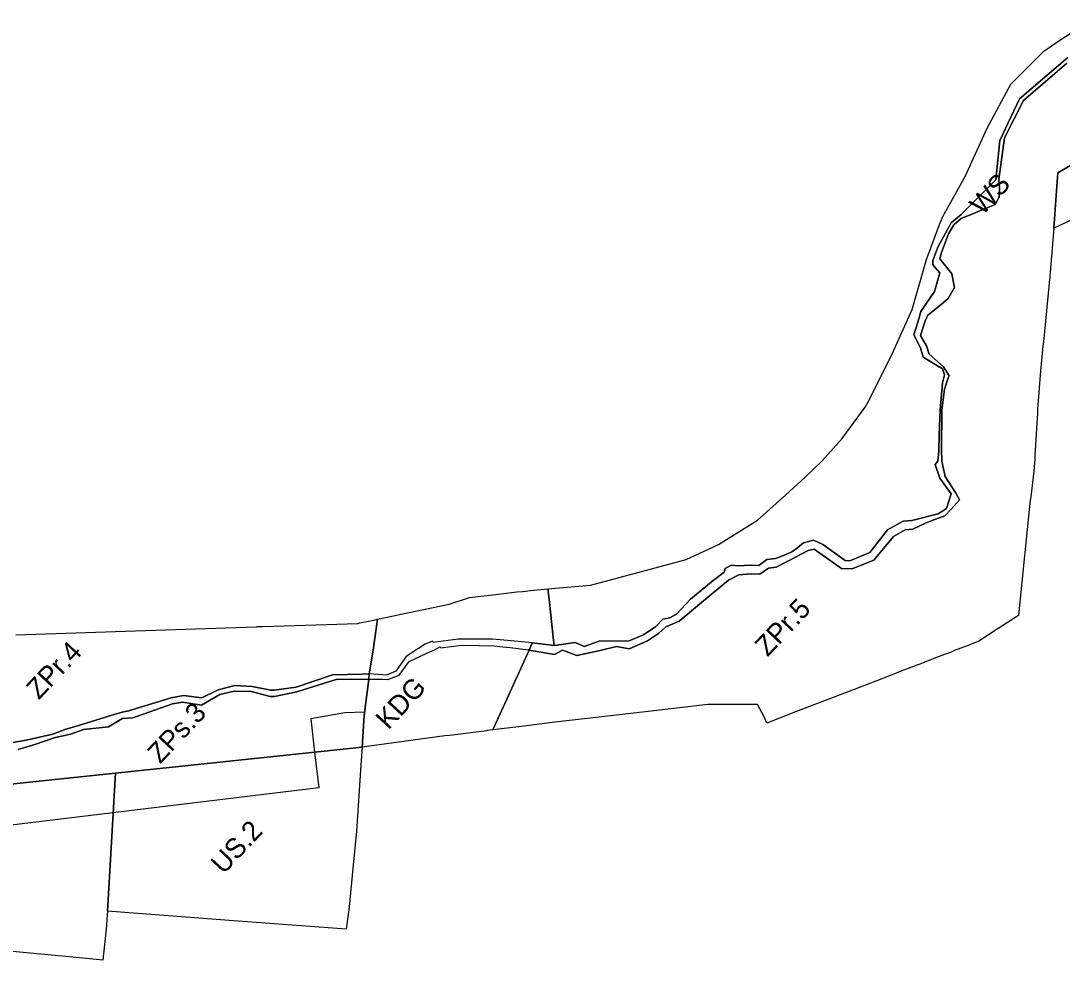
# Model space of a CAD drawing. Extents: x 7425782 to 7428854, y 5550411 to 5553074.
# Drawn here: x 7426386.8 to 7426859.1, y 5550939.3 to 5551365.3 of the extents above; entities that cross this region are included whole.
import ezdxf

# ---------------------------------------------------------------- set-up
doc = ezdxf.new("R2010")
doc.units = 0
for name, color, linetype in [('LIN_Linie rozgraniczajace WS', 7, 'Continuous'), ('LIN_linie_rozgraniczajace', 7, 'Continuous'), ('LIN_nieprzekraczalna linia zabudowy', 7, 'Continuous'), ('TXT_oznaczenia przeznaczen', 7, 'Continuous')]:
    doc.layers.add(name, color=color, linetype=linetype)

msp = doc.modelspace()

# ---------------------------------------------------------------- linework, layer by layer
at = {"layer": 'LIN_Linie rozgraniczajace WS'}
for points in [[(7426544.64, 5551066.75), (7426550.76, 5551066.7), (7426553.24, 5551066.62), (7426558.34, 5551068.56), (7426562.97, 5551074.77), (7426570.95, 5551078.5), (7426574.73, 5551080.15), (7426576.86, 5551081.45), (7426577.3, 5551080.86), (7426586.6, 5551082.15), (7426594.58, 5551081.99), (7426601.49, 5551081.78), (7426605.34, 5551081.36), (7426608.7, 5551081), (7426617.09, 5551079.96), (7426617.26, 5551079.93)], [(7426618.72, 5551083.15), (7426605.85, 5551084.33), (7426600.71, 5551084.81), (7426595.33, 5551084.81), (7426585.2, 5551084.85), (7426573.72, 5551083.35), (7426573.52, 5551084.02), (7426570.22, 5551082.64), (7426561.54, 5551076.92), (7426556.92, 5551070.28), (7426552.59, 5551068.57), (7426550.96, 5551068.63), (7426544.81, 5551069.07)]]:
    msp.add_lwpolyline(points, dxfattribs=at)
at = {"layer": 'LIN_linie_rozgraniczajace'}
for points in [[(7426861.62, 5551348.67), (7426839.69, 5551329.93), (7426830.84, 5551310.94), (7426828.92, 5551293.15), (7426813.19, 5551277.45), (7426808.67, 5551273.65), (7426802.7, 5551262.61), (7426800.34, 5551256.53), (7426800.44, 5551254.63), (7426803.55, 5551250.97), (7426801.13, 5551242.5), (7426795.01, 5551233.52), (7426794.5, 5551231.86), (7426794.19, 5551230.58), (7426791.84, 5551222.83), (7426794.76, 5551217.02), (7426796.02, 5551212.76), (7426804.8, 5551207.39), (7426805.63, 5551204.67), (7426804.72, 5551201.14), (7426803.73, 5551188.85), (7426803.34, 5551177.38), (7426803.16, 5551170.19), (7426802.7, 5551165.74), (7426802.04, 5551164.8), (7426801.52, 5551164.07), (7426803.58, 5551157.82), (7426808.73, 5551150.74), (7426806.57, 5551144.13), (7426802.84, 5551141.74), (7426790.86, 5551138.66), (7426787.01, 5551138.42), (7426779.87, 5551134.49), (7426771.89, 5551124.09), (7426762.83, 5551120.43), (7426760.72, 5551120.47), (7426750.52, 5551127.82), (7426746.29, 5551129.76), (7426741.82, 5551128.55), (7426738.96, 5551126.29), (7426736.47, 5551124.46), (7426733.43, 5551123.09), (7426728.99, 5551121.47), (7426725.12, 5551121.04), (7426721.48, 5551118.25), (7426717.63, 5551118.42), (7426712.16, 5551118.06), (7426708.98, 5551118.44), (7426706.16, 5551116.93), (7426705.81, 5551115.26), (7426700.73, 5551111.47), (7426690.46, 5551103.03), (7426684.12, 5551096.22), (7426681.09, 5551094.53), (7426678.02, 5551093.89), (7426674.76, 5551090.67), (7426669.15, 5551086.76), (7426662.62, 5551084.17), (7426649.14, 5551083.89), (7426642.26, 5551081.59), (7426638.9, 5551083.1), (7426638.25, 5551083.38), (7426628.65, 5551081.97), (7426628.2, 5551085.55), (7426626.49, 5551101.61), (7426625.83, 5551107.75), (7426645.13, 5551109.28), (7426647.39, 5551109.9), (7426666.64, 5551115.09), (7426688.49, 5551120.97), (7426703.26, 5551127.83), (7426720.86, 5551138.77), (7426733.58, 5551150.18), (7426742.45, 5551158.35), (7426750, 5551165.54), (7426759.3, 5551175.85), (7426769.77, 5551190.12), (7426771.1, 5551192.54), (7426781.46, 5551213.13), (7426791.01, 5551234.34), (7426797.59, 5551257.05), (7426803.48, 5551272.98), (7426804.91, 5551276.61), (7426815.07, 5551294.63), (7426824.99, 5551316.59), (7426835.75, 5551336.51), (7426850.74, 5551351.48), (7426858.52, 5551356.89), (7426871.59, 5551365.28)], [(7426861.25, 5551346.13), (7426841.49, 5551329.22), (7426832.91, 5551312.28), (7426830.27, 5551293.32), (7426830.69, 5551289.51), (7426830.48, 5551285.25), (7426829.17, 5551282.83), (7426828.35, 5551281.88), (7426823.87, 5551280.05), (7426819.56, 5551278.26), (7426813.3, 5551275.65), (7426809.94, 5551272.69), (7426807.56, 5551268.65), (7426804.38, 5551260.25), (7426803.58, 5551257.37), (7426809.07, 5551250.6), (7426810.19, 5551244.28), (7426807.41, 5551239.31), (7426805.15, 5551237.46), (7426797.98, 5551231.57), (7426797.47, 5551230.42), (7426796.99, 5551229.18), (7426794.77, 5551222.64), (7426797.6, 5551217.87), (7426798.74, 5551214.13), (7426805.2, 5551208.35), (7426807.82, 5551204.22), (7426807.36, 5551203.39), (7426805.74, 5551198.25), (7426804.47, 5551188.7), (7426804.41, 5551170.61), (7426804.42, 5551165.75), (7426804.91, 5551163.46), (7426805.93, 5551158.68), (7426810.68, 5551151.3), (7426812.47, 5551147.99), (7426808.75, 5551143.82), (7426805.91, 5551140.78), (7426800.17, 5551138.65), (7426797.4, 5551137.61), (7426791.28, 5551134.78), (7426787.8, 5551134.44), (7426782.56, 5551131.34), (7426773.59, 5551120.61), (7426764.95, 5551117.16), (7426763.79, 5551116.69), (7426758.93, 5551116.91), (7426746.53, 5551125.69), (7426743.84, 5551125.07), (7426740.69, 5551123.37), (7426734.89, 5551120.35), (7426729.34, 5551117.48), (7426725.82, 5551117.04), (7426721.99, 5551114.33), (7426718.04, 5551114.53), (7426712.46, 5551114.07), (7426707.71, 5551111.67), (7426695.53, 5551101.51), (7426685.36, 5551093.06), (7426679.24, 5551090.38), (7426675.99, 5551087.44), (7426670.94, 5551084.1), (7426662.68, 5551080.41), (7426656.97, 5551081.5), (7426649.6, 5551079.71), (7426638.93, 5551077.5), (7426632.43, 5551079.86), (7426628.84, 5551077.86), (7426617.26, 5551079.93), (7426618.72, 5551083.15), (7426628.65, 5551081.97), (7426638.25, 5551083.38), (7426638.9, 5551083.1), (7426642.26, 5551081.59), (7426649.14, 5551083.89), (7426662.62, 5551084.17), (7426669.15, 5551086.76), (7426674.76, 5551090.67), (7426678.02, 5551093.89), (7426681.09, 5551094.53), (7426684.12, 5551096.22), (7426690.46, 5551103.03), (7426700.73, 5551111.47), (7426705.81, 5551115.26), (7426706.16, 5551116.93), (7426708.98, 5551118.44), (7426712.16, 5551118.06), (7426717.63, 5551118.42), (7426721.48, 5551118.25), (7426725.12, 5551121.04), (7426728.99, 5551121.47), (7426733.43, 5551123.09), (7426736.47, 5551124.46), (7426738.96, 5551126.29), (7426741.82, 5551128.55), (7426746.29, 5551129.76), (7426750.52, 5551127.82), (7426760.72, 5551120.47), (7426762.83, 5551120.43), (7426771.89, 5551124.09), (7426779.87, 5551134.49), (7426787.01, 5551138.42), (7426790.86, 5551138.66), (7426802.84, 5551141.74), (7426806.57, 5551144.13), (7426808.73, 5551150.74), (7426803.58, 5551157.82), (7426801.52, 5551164.07), (7426802.04, 5551164.8), (7426802.7, 5551165.74), (7426803.16, 5551170.19), (7426803.34, 5551177.38), (7426803.73, 5551188.85), (7426804.72, 5551201.14), (7426805.63, 5551204.67), (7426804.8, 5551207.39), (7426796.02, 5551212.76), (7426794.76, 5551217.02), (7426791.84, 5551222.83), (7426794.19, 5551230.58), (7426794.5, 5551231.86), (7426795.01, 5551233.52), (7426801.13, 5551242.5), (7426803.55, 5551250.97), (7426800.44, 5551254.63), (7426800.34, 5551256.53), (7426802.7, 5551262.61), (7426808.67, 5551273.65), (7426813.19, 5551277.45), (7426828.92, 5551293.15), (7426830.84, 5551310.94), (7426839.69, 5551329.93), (7426861.62, 5551348.67)], [(7426904.68, 5551324.5), (7426857.13, 5551296.4), (7426856.53, 5551288.18), (7426855.24, 5551271.27), (7426853.69, 5551251.1), (7426853.53, 5551249.57), (7426853.41, 5551248.43), (7426853.4, 5551248.28), (7426853.39, 5551248.12), (7426853.05, 5551244.85), (7426851.13, 5551225.89), (7426850.52, 5551219.89), (7426850.28, 5551217.59), (7426850.16, 5551216.16), (7426849.31, 5551206.52), (7426848.45, 5551196.87), (7426848.44, 5551196.71), (7426848.27, 5551194.75), (7426847.94, 5551189.3), (7426847.81, 5551187.19), (7426847.56, 5551182.99), (7426846.94, 5551172.77), (7426846.68, 5551168.48), (7426846.68, 5551168.48), (7426846.62, 5551166.82), (7426846.61, 5551166.62), (7426846.16, 5551160.97), (7426845.97, 5551158.55), (7426844.78, 5551149.34), (7426844.78, 5551149.34), (7426844.56, 5551147.94), (7426844.35, 5551146.59), (7426839.63, 5551098.74), (7426839.32, 5551095.58), (7426830.06, 5551089.62), (7426821.26, 5551083.96), (7426821.26, 5551083.96), (7426820.17, 5551083.52), (7426815.95, 5551081.85), (7426814.84, 5551081.42), (7426813.03, 5551080.73), (7426811.89, 5551080.29), (7426810.23, 5551079.65), (7426809.33, 5551079.28), (7426807.46, 5551078.53), (7426805.75, 5551077.9), (7426804.52, 5551077.45), (7426801.59, 5551076.32), (7426798.79, 5551075.24), (7426798.79, 5551075.24), (7426795.99, 5551074.17), (7426794.44, 5551073.56), (7426793.2, 5551073.08), (7426790.4, 5551072), (7426787.6, 5551070.92), (7426784.8, 5551069.85), (7426781.89, 5551068.72), (7426781.89, 5551068.72), (7426764.7, 5551062.09), (7426738.14, 5551051.85), (7426725.06, 5551046.81), (7426723.92, 5551049.65), (7426720.88, 5551055.24), (7426720.87, 5551055.24), (7426709.59, 5551055.2), (7426707.73, 5551055.19), (7426698.32, 5551055.16), (7426668.78, 5551051.76), (7426648.9, 5551049.45), (7426629.02, 5551047.14), (7426613.82, 5551045.28), (7426613.82, 5551045.28), (7426607.33, 5551044.49), (7426600.85, 5551043.7), (7426617.26, 5551079.93), (7426628.84, 5551077.86), (7426632.43, 5551079.86), (7426638.93, 5551077.5), (7426649.6, 5551079.71), (7426656.97, 5551081.5), (7426662.68, 5551080.41), (7426670.94, 5551084.1), (7426675.99, 5551087.44), (7426679.24, 5551090.38), (7426685.36, 5551093.06), (7426695.53, 5551101.51), (7426707.71, 5551111.67), (7426712.46, 5551114.07), (7426718.04, 5551114.53), (7426721.99, 5551114.33), (7426725.82, 5551117.04), (7426729.34, 5551117.48), (7426734.89, 5551120.35), (7426740.69, 5551123.37), (7426743.84, 5551125.07), (7426746.53, 5551125.69), (7426758.93, 5551116.91), (7426763.79, 5551116.69), (7426764.95, 5551117.16), (7426773.59, 5551120.61), (7426782.56, 5551131.34), (7426787.8, 5551134.44), (7426791.28, 5551134.78), (7426797.4, 5551137.61), (7426800.17, 5551138.65), (7426805.91, 5551140.78), (7426808.75, 5551143.82), (7426812.47, 5551147.99), (7426810.68, 5551151.3), (7426805.93, 5551158.68), (7426804.91, 5551163.46), (7426804.42, 5551165.75), (7426804.41, 5551170.61), (7426804.47, 5551188.7), (7426805.74, 5551198.25), (7426807.36, 5551203.39), (7426807.82, 5551204.22), (7426805.2, 5551208.35), (7426798.74, 5551214.13), (7426797.6, 5551217.87), (7426794.77, 5551222.64), (7426796.99, 5551229.18), (7426797.47, 5551230.42), (7426797.98, 5551231.57), (7426805.15, 5551237.46), (7426807.41, 5551239.31), (7426810.19, 5551244.28), (7426809.07, 5551250.6), (7426803.58, 5551257.37), (7426804.38, 5551260.25), (7426807.56, 5551268.65), (7426809.94, 5551272.69), (7426813.3, 5551275.65), (7426819.56, 5551278.26), (7426823.87, 5551280.05), (7426828.35, 5551281.88), (7426829.17, 5551282.83), (7426830.48, 5551285.25), (7426830.69, 5551289.51), (7426830.27, 5551293.32), (7426832.91, 5551312.28), (7426841.49, 5551329.22), (7426861.25, 5551346.13)], [(7426384.54, 5551086.82), (7426470.47, 5551089.73), (7426493.6, 5551090.52), (7426493.61, 5551090.52), (7426493.63, 5551090.52), (7426493.9, 5551090.53), (7426496.73, 5551090.62), (7426539.61, 5551092), (7426540.15, 5551092.11), (7426540.58, 5551092.2), (7426546.85, 5551093.52), (7426546.85, 5551093.52), (7426548.52, 5551093.87), (7426548.52, 5551093.87), (7426546.57, 5551079.86), (7426544.81, 5551069.07), (7426541.58, 5551068.93), (7426528.11, 5551068.68), (7426511.67, 5551063.04), (7426501.67, 5551061.71), (7426500.1, 5551061.75), (7426491.64, 5551063.42), (7426483.83, 5551063.82), (7426476.23, 5551061.93), (7426468.87, 5551058.26), (7426460.57, 5551059.35), (7426455.02, 5551058.25), (7426437.15, 5551052.76), (7426435.78, 5551052.36), (7426432.68, 5551051.7), (7426429.6, 5551050.85), (7426411.99, 5551045.36), (7426407.25, 5551044.02), (7426401.24, 5551041.78), (7426389.24, 5551039.02), (7426371.6, 5551036.01)], [(7426371.6, 5551036.01), (7426389.24, 5551039.02), (7426401.24, 5551041.78), (7426407.25, 5551044.02), (7426411.99, 5551045.36), (7426429.6, 5551050.85), (7426432.68, 5551051.7), (7426435.78, 5551052.36), (7426437.15, 5551052.76), (7426455.02, 5551058.25), (7426460.57, 5551059.35), (7426468.87, 5551058.26), (7426476.23, 5551061.93), (7426483.83, 5551063.82), (7426491.64, 5551063.42), (7426500.1, 5551061.75), (7426501.67, 5551061.71), (7426511.67, 5551063.04), (7426528.11, 5551068.68), (7426541.58, 5551068.93), (7426544.81, 5551069.07), (7426544.64, 5551066.75), (7426529.8, 5551066.56), (7426511.95, 5551061.03), (7426501.81, 5551058.79), (7426499.93, 5551058.8), (7426491.26, 5551061.16), (7426483.56, 5551061.24), (7426477.09, 5551059.8), (7426468.73, 5551054.95), (7426460.18, 5551056.34), (7426455.57, 5551055.52), (7426437.53, 5551049.25), (7426432.84, 5551048.85), (7426431.04, 5551047.75), (7426426.6, 5551045.05), (7426415.16, 5551043.94), (7426409.34, 5551041.7), (7426401.92, 5551040.06), (7426393.57, 5551037.22), (7426385.51, 5551034.78)], [(7426385.51, 5551034.78), (7426393.57, 5551037.22), (7426401.92, 5551040.06), (7426409.34, 5551041.7), (7426415.16, 5551043.94), (7426426.6, 5551045.05), (7426431.04, 5551047.75), (7426432.84, 5551048.85), (7426437.53, 5551049.25), (7426455.57, 5551055.52), (7426460.18, 5551056.34), (7426468.73, 5551054.95), (7426477.09, 5551059.8), (7426483.56, 5551061.24), (7426491.26, 5551061.16), (7426499.93, 5551058.8), (7426501.81, 5551058.79), (7426511.95, 5551061.03), (7426529.8, 5551066.56), (7426544.64, 5551066.75), (7426542.51, 5551050.17), (7426541.56, 5551035.89), (7426429.66, 5551024.14), (7426295.49, 5551010.06)]]:
    msp.add_lwpolyline(points, dxfattribs=at)
for points in [[(7426861.45, 5551274.13), (7426855.24, 5551271.27), (7426856.53, 5551288.18), (7426857.13, 5551296.4), (7426904.68, 5551324.5), (7426904.25, 5551317.27), (7426902.48, 5551312.15), (7426901.55, 5551309.45), (7426897.29, 5551292.77), (7426891.44, 5551287.93), (7426887.61, 5551286.17), (7426886.32, 5551285.58), (7426878.27, 5551281.87), (7426877.37, 5551281.46), (7426877.37, 5551281.46), (7426868.27, 5551277.27)], [(7426628.2, 5551085.55), (7426628.65, 5551081.97), (7426618.72, 5551083.15), (7426617.26, 5551079.93), (7426600.85, 5551043.7), (7426598.55, 5551043.42), (7426598.09, 5551043.36), (7426598.09, 5551043.35), (7426581.29, 5551041.24), (7426579.14, 5551040.97), (7426541.56, 5551035.89), (7426541.56, 5551035.89), (7426542.51, 5551050.17), (7426544.64, 5551066.75), (7426544.81, 5551069.07), (7426546.57, 5551079.86), (7426548.52, 5551093.87), (7426548.52, 5551093.87), (7426556.52, 5551095.56), (7426558.52, 5551095.98), (7426581.03, 5551100.72), (7426590.32, 5551103.68), (7426600.77, 5551104.94), (7426600.81, 5551104.94), (7426611.8, 5551106.25), (7426614.37, 5551106.51), (7426614.49, 5551106.51), (7426617.99, 5551106.87), (7426625.83, 5551107.75), (7426626.49, 5551101.61)], [(7426534.34, 5550953.28), (7426534.34, 5550953.28), (7426481.27, 5550957.33), (7426426.02, 5550961.54), (7426429.66, 5551024.14), (7426541.56, 5551035.89), (7426541.15, 5551029.79), (7426541.01, 5551027.76), (7426541.01, 5551027.76), (7426539.01, 5550997.83), (7426537.35, 5550980.9), (7426535.63, 5550963.43)], [(7426425.64, 5550954.9), (7426424, 5550939.27), (7426410.3, 5550940.56), (7426368.28, 5550944.5), (7426359.7, 5550941.77), (7426358.59, 5550941.42), (7426358.97, 5550946.87), (7426357.5, 5550946.8), (7426349.51, 5550946.41), (7426349.44, 5550944.41), (7426349.38, 5550942.63), (7426289.12, 5550948.57), (7426289.39, 5550951.87), (7426289.51, 5550952.33), (7426295.49, 5551010.06), (7426429.66, 5551024.14), (7426426.02, 5550961.54), (7426426.02, 5550961.54), (7426425.81, 5550957.91)]]:
    msp.add_lwpolyline(points, close=True, dxfattribs=at)
at = {"layer": 'LIN_nieprzekraczalna linia zabudowy'}
msp.add_lwpolyline([(7426542.71, 5551051.69), (7426533.71, 5551051.41), (7426518.28, 5551048.79), (7426520.05, 5551033.63), (7426521.96, 5551017.38), (7426371.04, 5550999.14), (7426293.78, 5550993.52)], dxfattribs=at)

# ---------------------------------------------------------------- texts
at = {"layer": 'TXT_oznaczenia przeznaczen'}
for s, rotation, p in [('WS', 46.7736, (7426822.89, 5551276.68)), ('ZPr.5', 46.7736, (7426725.47, 5551076.56)), ('ZPr.4', 46.7736, (7426394.97, 5551057.09)), ('KDG', 47.3454, (7426553.52, 5551043.36)), ('ZPs.3', 46.7736, (7426449.95, 5551027.99)), ('US.2', 46.7736, (7426478.67, 5550977.86))]:
    msp.add_text(s, height=9, rotation=rotation, dxfattribs=at).set_placement(p)

doc.saveas('drawing.dxf')
